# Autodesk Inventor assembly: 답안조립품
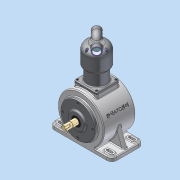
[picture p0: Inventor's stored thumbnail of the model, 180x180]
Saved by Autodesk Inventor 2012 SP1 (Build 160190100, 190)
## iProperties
Created: 2015-06
Part Number: 답안조립품
Document SubType Name: Assembly
Designer: Administrator
Author: Administrator
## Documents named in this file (15)
- C:\Users\Administrator\Desktop\450605V1024\답안조립품.iam
- C:\Users\Administrator\Desktop\450605V1024\본체.ipt
- C:\Users\Administrator\Desktop\450605V1024\실린더.ipt
- C:\Users\Administrator\Desktop\450605V1024\실린더헤드.ipt
- C:\Users\Administrator\Desktop\450605V1024\메인커버.ipt
- C:\Users\Administrator\Desktop\450605V1024\메인 크랭크 축-구동부.ipt
- C:\Users\Administrator\Desktop\450605V1024\크랭크 서브축.ipt
- C:\Users\Administrator\Desktop\450605V1024\커넥팅 로드.ipt
- C:\Users\Administrator\Desktop\450605V1024\피스톤.ipt
- C:\Users\Administrator\Desktop\450605V1024\베어링 6204.ipt
- C:\Users\Administrator\Desktop\450605V1024\베어링 NA 4902.ipt
- C:\Users\Administrator\Desktop\450605V1024\오일실.ipt
- C:\Users\Administrator\Desktop\450605V1024\피스톤 핀.ipt
- C:\Users\Administrator\Desktop\450605V1024\M5x0.8.ipt
- C:\Users\Administrator\Desktop\450605V1024\M4x0.7.ipt
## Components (14 placed, 4 different names)
1. 피스톤:1
2. 피스톤 핀:1
3. M5x0.8:1
4. M5x0.8:2
5. M5x0.8:3
6. M5x0.8:4
7. M4x0.7:1
8. M4x0.7:3
9. M4x0.7:4
10. M4x0.7:5
11. M4x0.7:2
12. M4x0.7:6
13. M4x0.7:7
14. M4x0.7:8
